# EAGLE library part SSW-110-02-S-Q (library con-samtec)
THROUGH-HOLE .025" SQ POST SOCKET Source: Samtec SSW.pdf
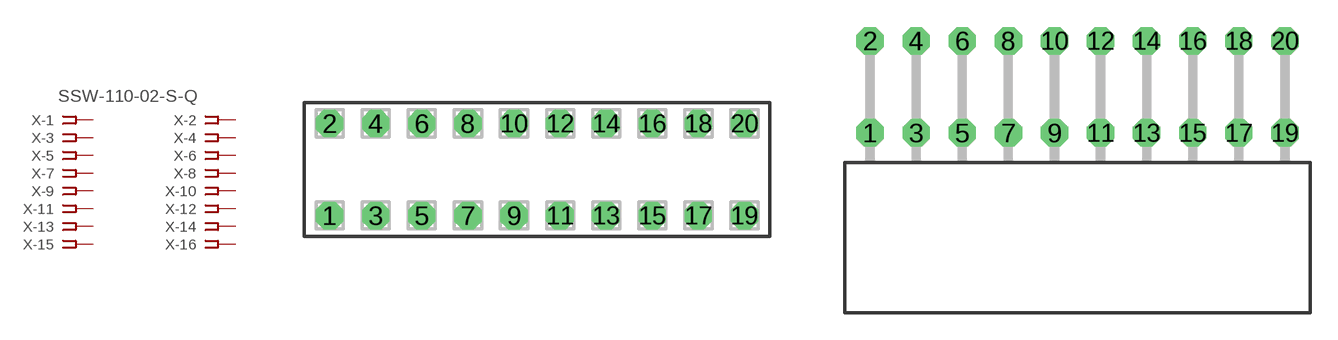
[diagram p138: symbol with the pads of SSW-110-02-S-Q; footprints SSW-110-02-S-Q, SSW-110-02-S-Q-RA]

Designator prefix X; gates -1=FPINV -2=FPIN -3=FPIN -4=FPIN -5=FPIN -6=FPIN -7=FPIN -8=FPIN -9=FPIN -10=FPIN -11=FPIN -12=FPIN -13=FPIN -14=FPIN -15=FPIN -16=FPIN -17=FPIN -18=FPIN -19=FPIN -20=FPIN

## SSW-110-02-S-Q (MPN: SSW-110-02-S-Q; OC_FARNELL: unknown; OC_NEWARK: 82P5232)  [SSW-110-02-S-Q]
1  -1:1  pas
2  -2:1  pas
3  -3:1  pas
4  -4:1  pas
5  -5:1  pas
6  -6:1  pas
7  -7:1  pas
8  -8:1  pas
9  -9:1  pas
10  -10:1  pas
11  -11:1  pas
12  -12:1  pas
13  -13:1  pas
14  -14:1  pas
15  -15:1  pas
16  -16:1  pas
17  -17:1  pas
18  -18:1  pas
19  -19:1  pas
20  -20:1  pas

## SSW-110-02-S-QRA (MPN: SSW-110-02-S-Q-RA; OC_FARNELL: unknown; OC_NEWARK: 82P5234)  [SSW-110-02-S-Q-RA]
Pads as for SSW-110-02-S-Q

## Footprint SSW-110-02-S-Q (pad centres in mm)
THROUGH-HOLE .025" SQ POST SOCKET Source: Samtec SSW.pdf
drill 1 pad 1.5 octagon: 1 -11.43,-2.54; 2 -11.43,2.54; 3 -8.89,-2.54; 4 -8.89,2.54; 5 -6.35,-2.54; 6 -6.35,2.54; 7 -3.81,-2.54; 8 -3.81,2.54; 9 -1.27,-2.54; 10 -1.27,2.54; 11 1.27,-2.54; 12 1.27,2.54; 13 3.81,-2.54; 14 3.81,2.54; 15 6.35,-2.54; 16 6.35,2.54; 17 8.89,-2.54; 18 8.89,2.54; 19 11.43,-2.54; 20 11.43,2.54

## Footprint SSW-110-02-S-Q-RA (pad centres in mm)
THROUGH-HOLE .025" SQ POST SOCKET Source: Samtec SSW.pdf
drill 1 pad 1.5 octagon: 1 -11.43,1.524; 2 -11.43,6.604; 3 -8.89,1.524; 4 -8.89,6.604; 5 -6.35,1.524; 6 -6.35,6.604; 7 -3.81,1.524; 8 -3.81,6.604; 9 -1.27,1.524; 10 -1.27,6.604; 11 1.27,1.524; 12 1.27,6.604; 13 3.81,1.524; 14 3.81,6.604; 15 6.35,1.524; 16 6.35,6.604; 17 8.89,1.524; 18 8.89,6.604; 19 11.43,1.524; 20 11.43,6.604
